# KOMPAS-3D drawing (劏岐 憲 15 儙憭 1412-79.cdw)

Referenced files: Диск.cdw
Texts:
  Диск
  Ra 3,2
  Ra 6,3
  Ra 1,6
  1. НВ 163...299
  2. Класс  точности отливки - III по ГОСТ 1855-55
  3. h14; H14;  JT14 2
  4. Неуказанные радиусы скруглений  2 мм
  СЧ 15 ГОСТ 1412-79
Dimensions and other numbers on the sheet: 255; 8отв; 11; 3отв; 17; 141; 230; 205; 40; 45; 80; 42; 15; 9; 6; 4; 10; 30; 184; 192; 3; 1,6; 0,05; 1:2; 1; 0; 2; 5; 7; 8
